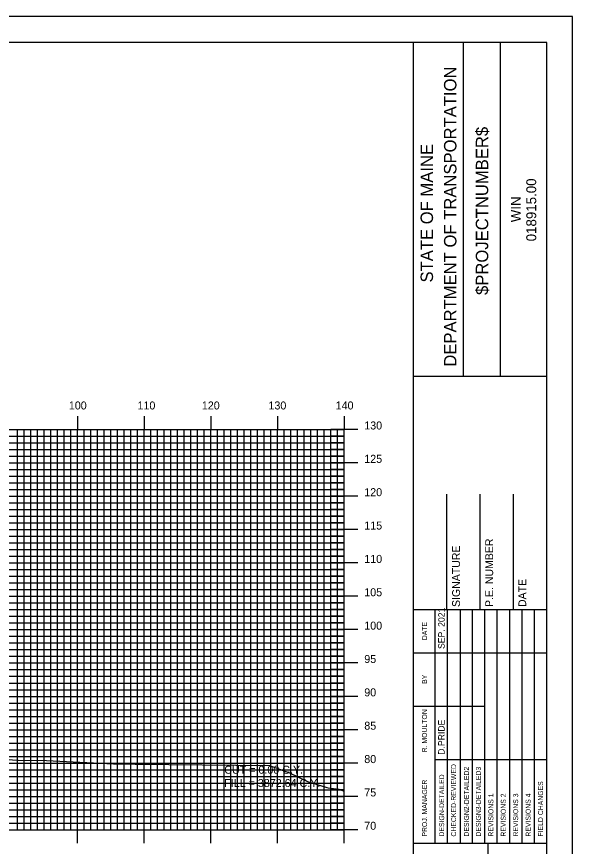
# Model space of a CAD drawing. Extents: x 858291 to 858634, y 364765 to 364985.
# Drawn here: x 858547.2 to 858630.5, y 364860.8 to 364985.2 of the extents above; entities that cross this region are included whole.
import ezdxf

# ---------------------------------------------------------------- set-up
doc = ezdxf.new("R2010")
doc.units = 0
for name, color, linetype in [('BORDER', 7, 'Continuous'), ('D_Text_Standard', 7, 'Continuous'), ('H_V ANNOTATION', 7, 'Continuous'), ('MAJOR', 7, 'Continuous'), ('MINOR', 7, 'Continuous'), ('PLOT BOUNDARY', 7, 'Continuous'), ('S_Roadway_Centerline', 7, 'Continuous')]:
    doc.layers.add(name, color=color, linetype=linetype)

msp = doc.modelspace()

# ---------------------------------------------------------------- linework, layer by layer
at = {"layer": 'BORDER'}
for p, q in [((858606.73, 364771.3), (858606.73, 364981.3)), ((858614.19, 364931.3), (858614.19, 364981.3)), ((858619.78, 364931.3), (858619.78, 364981.3)), ((858606.74, 364931.29), (858626.73, 364931.29)), ((858611.73, 364896.31), (858611.73, 364913.6)), ((858616.73, 364896.31), (858616.73, 364913.6)), ((858621.73, 364896.31), (858621.73, 364913.6)), ((858606.73, 364896.31), (858626.73, 364896.31)), ((858606.73, 364861.31), (858626.73, 364861.31)), ((858617.92, 364791.31), (858617.92, 364861.31))]:
    msp.add_line(p, q, dxfattribs=at)
msp.add_lwpolyline([(858306.73, 364771.3), (858626.73, 364771.3), (858626.73, 364981.3), (858306.73, 364981.3)], close=True, dxfattribs=at)
for points in [[(858609.96, 364889.81), (858609.96, 364896.31)], [(858611.83, 364861.31), (858611.83, 364896.31)], [(858613.69, 364896.31), (858613.69, 364861.31)], [(858615.56, 364861.31), (858615.56, 364896.31)], [(858617.42, 364861.31), (858617.42, 364896.31)], [(858619.28, 364861.31), (858619.28, 364896.31)], [(858621.15, 364861.31), (858621.15, 364896.31)], [(858623.01, 364861.31), (858623.01, 364896.31)], [(858624.87, 364861.31), (858624.87, 364896.31)], [(858609.97, 364861.31), (858609.97, 364894.9)], [(858606.73, 364889.81), (858626.73, 364889.81)], [(858606.73, 364881.81), (858609.97, 364881.81)], [(858609.96, 364881.81), (858617.42, 364881.81)], [(858609.96, 364873.81), (858626.73, 364873.81)]]:
    msp.add_lwpolyline(points, dxfattribs=at)
at = {"layer": 'MAJOR'}
for p, q in [((858556.33, 364925.31), (858556.33, 364923.3)), ((858566.33, 364925.31), (858566.33, 364923.3)), ((858576.33, 364925.31), (858576.33, 364923.3)), ((858586.33, 364925.31), (858586.33, 364923.3)), ((858596.33, 364925.31), (858596.33, 364923.3)), ((858316.33, 364923.3), (858596.33, 364923.3)), ((858316.33, 364923.3), (858596.33, 364923.3)), ((858556.33, 364863.3), (858556.33, 364923.3)), ((858566.33, 364863.3), (858566.33, 364923.3)), ((858576.33, 364863.3), (858576.33, 364923.3)), ((858586.33, 364863.3), (858586.33, 364923.3)), ((858598.34, 364923.3), (858594.33, 364923.3)), ((858596.33, 364863.3), (858596.33, 364923.3)), ((858596.33, 364863.3), (858596.33, 364923.3)), ((858316.33, 364918.3), (858596.33, 364918.3)), ((858598.34, 364918.3), (858594.33, 364918.3)), ((858316.33, 364913.3), (858596.33, 364913.3)), ((858598.34, 364913.3), (858594.33, 364913.3)), ((858316.33, 364908.3), (858596.33, 364908.3)), ((858598.34, 364908.3), (858594.33, 364908.3)), ((858316.33, 364903.3), (858596.33, 364903.3)), ((858598.34, 364903.3), (858594.33, 364903.3)), ((858316.33, 364898.3), (858596.33, 364898.3)), ((858598.34, 364898.3), (858594.33, 364898.3)), ((858316.33, 364893.3), (858596.33, 364893.3)), ((858598.34, 364893.3), (858594.33, 364893.3)), ((858316.33, 364888.3), (858596.33, 364888.3)), ((858598.34, 364888.3), (858594.33, 364888.3)), ((858316.33, 364883.3), (858596.33, 364883.3)), ((858598.34, 364883.3), (858594.33, 364883.3)), ((858316.33, 364878.3), (858596.33, 364878.3)), ((858598.34, 364878.3), (858594.33, 364878.3)), ((858316.33, 364873.3), (858596.33, 364873.3)), ((858598.34, 364873.3), (858594.33, 364873.3)), ((858316.33, 364868.3), (858596.33, 364868.3)), ((858598.34, 364868.3), (858594.33, 364868.3)), ((858316.33, 364863.3), (858596.33, 364863.3)), ((858316.33, 364863.3), (858596.33, 364863.3)), ((858556.33, 364861.3), (858556.33, 364863.3)), ((858566.33, 364861.3), (858566.33, 364863.3)), ((858576.33, 364861.3), (858576.33, 364863.3)), ((858586.33, 364861.3), (858586.33, 364863.3)), ((858598.34, 364863.3), (858594.33, 364863.3)), ((858596.33, 364861.3), (858596.33, 364863.3))]:
    msp.add_line(p, q, dxfattribs=at)
at = {"layer": 'MINOR'}
for p, q in [((858547.33, 364863.3), (858547.33, 364923.3)), ((858548.33, 364863.3), (858548.33, 364923.3)), ((858549.33, 364863.3), (858549.33, 364923.3)), ((858550.33, 364863.3), (858550.33, 364923.3)), ((858551.33, 364863.3), (858551.33, 364923.3)), ((858552.33, 364863.3), (858552.33, 364923.3)), ((858553.33, 364863.3), (858553.33, 364923.3)), ((858554.33, 364863.3), (858554.33, 364923.3)), ((858555.33, 364863.3), (858555.33, 364923.3)), ((858557.33, 364863.3), (858557.33, 364923.3)), ((858558.33, 364863.3), (858558.33, 364923.3)), ((858559.33, 364863.3), (858559.33, 364923.3)), ((858560.33, 364863.3), (858560.33, 364923.3)), ((858561.33, 364863.3), (858561.33, 364923.3)), ((858562.33, 364863.3), (858562.33, 364923.3)), ((858563.33, 364863.3), (858563.33, 364923.3)), ((858564.33, 364863.3), (858564.33, 364923.3)), ((858565.33, 364863.3), (858565.33, 364923.3)), ((858567.33, 364863.3), (858567.33, 364923.3)), ((858568.33, 364863.3), (858568.33, 364923.3)), ((858569.33, 364863.3), (858569.33, 364923.3)), ((858570.33, 364863.3), (858570.33, 364923.3)), ((858571.33, 364863.3), (858571.33, 364923.3)), ((858572.33, 364863.3), (858572.33, 364923.3)), ((858573.33, 364863.3), (858573.33, 364923.3)), ((858574.33, 364863.3), (858574.33, 364923.3)), ((858575.33, 364863.3), (858575.33, 364923.3)), ((858577.33, 364863.3), (858577.33, 364923.3)), ((858578.33, 364863.3), (858578.33, 364923.3)), ((858579.33, 364863.3), (858579.33, 364923.3)), ((858580.33, 364863.3), (858580.33, 364923.3)), ((858581.33, 364863.3), (858581.33, 364923.3)), ((858582.33, 364863.3), (858582.33, 364923.3)), ((858583.33, 364863.3), (858583.33, 364923.3)), ((858584.33, 364863.3), (858584.33, 364923.3)), ((858585.33, 364863.3), (858585.33, 364923.3)), ((858587.33, 364863.3), (858587.33, 364923.3)), ((858588.33, 364863.3), (858588.33, 364923.3)), ((858589.33, 364863.3), (858589.33, 364923.3)), ((858590.33, 364863.3), (858590.33, 364923.3)), ((858591.33, 364863.3), (858591.33, 364923.3)), ((858592.33, 364863.3), (858592.33, 364923.3)), ((858593.33, 364863.3), (858593.33, 364923.3)), ((858594.33, 364863.3), (858594.33, 364923.3)), ((858595.33, 364863.3), (858595.33, 364923.3)), ((858316.33, 364922.3), (858596.33, 364922.3)), ((858596.33, 364922.3), (858594.33, 364922.3)), ((858316.33, 364921.3), (858596.33, 364921.3)), ((858596.33, 364921.3), (858594.33, 364921.3)), ((858316.33, 364920.3), (858596.33, 364920.3)), ((858596.33, 364920.3), (858594.33, 364920.3)), ((858316.33, 364919.3), (858596.33, 364919.3)), ((858596.33, 364919.3), (858594.33, 364919.3)), ((858316.33, 364917.3), (858596.33, 364917.3)), ((858596.33, 364917.3), (858594.33, 364917.3)), ((858316.33, 364916.3), (858596.33, 364916.3)), ((858596.33, 364916.3), (858594.33, 364916.3)), ((858316.33, 364915.3), (858596.33, 364915.3)), ((858596.33, 364915.3), (858594.33, 364915.3)), ((858316.33, 364914.3), (858596.33, 364914.3)), ((858596.33, 364914.3), (858594.33, 364914.3)), ((858316.33, 364912.3), (858596.33, 364912.3)), ((858596.33, 364912.3), (858594.33, 364912.3)), ((858316.33, 364911.3), (858596.33, 364911.3)), ((858596.33, 364911.3), (858594.33, 364911.3)), ((858316.33, 364910.3), (858596.33, 364910.3)), ((858596.33, 364910.3), (858594.33, 364910.3)), ((858316.33, 364909.3), (858596.33, 364909.3)), ((858596.33, 364909.3), (858594.33, 364909.3)), ((858316.33, 364907.3), (858596.33, 364907.3)), ((858596.33, 364907.3), (858594.33, 364907.3)), ((858316.33, 364906.3), (858596.33, 364906.3)), ((858596.33, 364906.3), (858594.33, 364906.3)), ((858316.33, 364905.3), (858596.33, 364905.3)), ((858596.33, 364905.3), (858594.33, 364905.3)), ((858316.33, 364904.3), (858596.33, 364904.3)), ((858596.33, 364904.3), (858594.33, 364904.3)), ((858316.33, 364902.3), (858596.33, 364902.3)), ((858596.33, 364902.3), (858594.33, 364902.3)), ((858316.33, 364901.3), (858596.33, 364901.3)), ((858596.33, 364901.3), (858594.33, 364901.3)), ((858316.33, 364900.3), (858596.33, 364900.3)), ((858596.33, 364900.3), (858594.33, 364900.3)), ((858316.33, 364899.3), (858596.33, 364899.3)), ((858596.33, 364899.3), (858594.33, 364899.3)), ((858316.33, 364897.3), (858596.33, 364897.3)), ((858596.33, 364897.3), (858594.33, 364897.3)), ((858316.33, 364896.3), (858596.33, 364896.3)), ((858596.33, 364896.3), (858594.33, 364896.3)), ((858316.33, 364895.3), (858596.33, 364895.3)), ((858596.33, 364895.3), (858594.33, 364895.3)), ((858316.33, 364894.3), (858596.33, 364894.3)), ((858596.33, 364894.3), (858594.33, 364894.3)), ((858316.33, 364892.3), (858596.33, 364892.3)), ((858596.33, 364892.3), (858594.33, 364892.3)), ((858316.33, 364891.3), (858596.33, 364891.3)), ((858596.33, 364891.3), (858594.33, 364891.3)), ((858316.33, 364890.3), (858596.33, 364890.3)), ((858596.33, 364890.3), (858594.33, 364890.3)), ((858316.33, 364889.3), (858596.33, 364889.3)), ((858596.33, 364889.3), (858594.33, 364889.3)), ((858316.33, 364887.3), (858596.33, 364887.3)), ((858596.33, 364887.3), (858594.33, 364887.3)), ((858316.33, 364886.3), (858596.33, 364886.3)), ((858596.33, 364886.3), (858594.33, 364886.3)), ((858316.33, 364885.3), (858596.33, 364885.3)), ((858596.33, 364885.3), (858594.33, 364885.3)), ((858316.33, 364884.3), (858596.33, 364884.3)), ((858596.33, 364884.3), (858594.33, 364884.3)), ((858316.33, 364882.3), (858596.33, 364882.3)), ((858596.33, 364882.3), (858594.33, 364882.3)), ((858316.33, 364881.3), (858596.33, 364881.3)), ((858596.33, 364881.3), (858594.33, 364881.3)), ((858316.33, 364880.3), (858596.33, 364880.3)), ((858596.33, 364880.3), (858594.33, 364880.3)), ((858316.33, 364879.3), (858596.33, 364879.3)), ((858596.33, 364879.3), (858594.33, 364879.3)), ((858316.33, 364877.3), (858596.33, 364877.3)), ((858596.33, 364877.3), (858594.33, 364877.3)), ((858316.33, 364876.3), (858596.33, 364876.3)), ((858596.33, 364876.3), (858594.33, 364876.3)), ((858316.33, 364875.3), (858596.33, 364875.3)), ((858596.33, 364875.3), (858594.33, 364875.3)), ((858316.33, 364874.3), (858596.33, 364874.3)), ((858596.33, 364874.3), (858594.33, 364874.3)), ((858316.33, 364872.3), (858596.33, 364872.3)), ((858596.33, 364872.3), (858594.33, 364872.3)), ((858316.33, 364871.3), (858596.33, 364871.3)), ((858596.33, 364871.3), (858594.33, 364871.3)), ((858316.33, 364870.3), (858596.33, 364870.3)), ((858596.33, 364870.3), (858594.33, 364870.3)), ((858316.33, 364869.3), (858596.33, 364869.3)), ((858596.33, 364869.3), (858594.33, 364869.3)), ((858316.33, 364867.3), (858596.33, 364867.3)), ((858596.33, 364867.3), (858594.33, 364867.3)), ((858316.33, 364866.3), (858596.33, 364866.3)), ((858596.33, 364866.3), (858594.33, 364866.3)), ((858316.33, 364865.3), (858596.33, 364865.3)), ((858596.33, 364865.3), (858594.33, 364865.3)), ((858316.33, 364864.3), (858596.33, 364864.3)), ((858596.33, 364864.3), (858594.33, 364864.3))]:
    msp.add_line(p, q, dxfattribs=at)
at = {"layer": 'PLOT BOUNDARY'}
msp.add_lwpolyline([(858290.55, 364765.18), (858630.55, 364765.18), (858630.55, 364985.18), (858290.55, 364985.18)], close=True, dxfattribs=at)
at = {"layer": 'S_Roadway_Centerline'}
msp.add_lwpolyline([(858541.53, 364874.09), (858547.42, 364873.73), (858551.67, 364873.66), (858561.7, 364873.19), (858564.99, 364873.12), (858585.12, 364872.95), (858588.09, 364871.85), (858590.8, 364870.53), (858593.73, 364869.66), (858593.93, 364869.59), (858595.49, 364869.41), (858596.33, 364869.1)], dxfattribs=at)

# ---------------------------------------------------------------- texts
at = {"layer": 'BORDER'}
for s, height, p in [('DEPARTMENT OF TRANSPORTATION', 1.8635, (858613.15, 364932.71)), ('$PROJECTNUMBER$', 1.8635, (858617.92, 364943.46)), ('STATE OF MAINE', 1.8635, (858609.64, 364945.33)), ('018915.00', 1.491, (858625.12, 364951.5)), ('WIN', 1.491, (858622.81, 364954.36)), ('P.E. NUMBER', 1.1811, (858618.66, 364896.69)), ('SIGNATURE', 1.181, (858613.69, 364896.69)), ('DATE', 1.181, (858623.62, 364896.69)), ('SEP. 2021', 0.969, (858611.38, 364890.4)), ('DATE', 0.743, (858608.74, 364891.72)), ('BY', 0.743, (858608.74, 364885.18)), ('R. MOULTON', 0.745, (858608.74, 364874.91)), ('D.PRIDE', 0.969, (858611.38, 364874.55)), ('CHECKED-REVIEWED', 0.7455, (858613.1, 364862.28)), ('DESIGN2-DETAILED2', 0.7455, (858615.03, 364862.28)), ('DESIGN3-DETAILED3', 0.7455, (858616.82, 364862.28)), ('DESIGN-DETAILED', 0.7455, (858611.31, 364862.28)), ('PROJ. MANAGER', 0.7455, (858608.74, 364862.28)), ('FIELD CHANGES', 0.7455, (858626.14, 364862.28)), ('REVISIONS 1', 0.7455, (858618.69, 364862.28)), ('REVISIONS 2', 0.7455, (858620.55, 364862.28)), ('REVISIONS 3', 0.7455, (858622.41, 364862.28)), ('REVISIONS 4', 0.7455, (858624.28, 364862.28))]:
    msp.add_text(s, height=height, rotation=90, dxfattribs=at).set_placement(p)
at = {"layer": 'D_Text_Standard'}
for s, p in [('CUT = 0.00 C.Y.', (858578.33, 364871.7)), ('FILL = 3872.64 C.Y.', (858578.33, 364869.71))]:
    msp.add_text(s, height=1.2, dxfattribs=at).set_placement(p)
at = {"layer": 'H_V ANNOTATION'}
for s, p in [('100', (858555.02, 364926.3)), ('110', (858565.32, 364926.3)), ('120', (858574.97, 364926.3)), ('130', (858584.96, 364926.3)), ('140', (858595.04, 364926.3)), ('130', (858599.33, 364923.3)), ('125', (858599.33, 364918.3)), ('120', (858599.33, 364913.3)), ('115', (858599.33, 364908.3)), ('110', (858599.33, 364903.3)), ('105', (858599.33, 364898.3)), ('100', (858599.33, 364893.3)), ('95', (858599.33, 364888.3)), ('90', (858599.33, 364883.3)), ('85', (858599.33, 364878.3)), ('80', (858599.33, 364873.3)), ('75', (858599.33, 364868.3)), ('70', (858599.33, 364863.3))]:
    msp.add_text(s, height=1.2, dxfattribs=at).set_placement(p)

doc.saveas('drawing.dxf')
